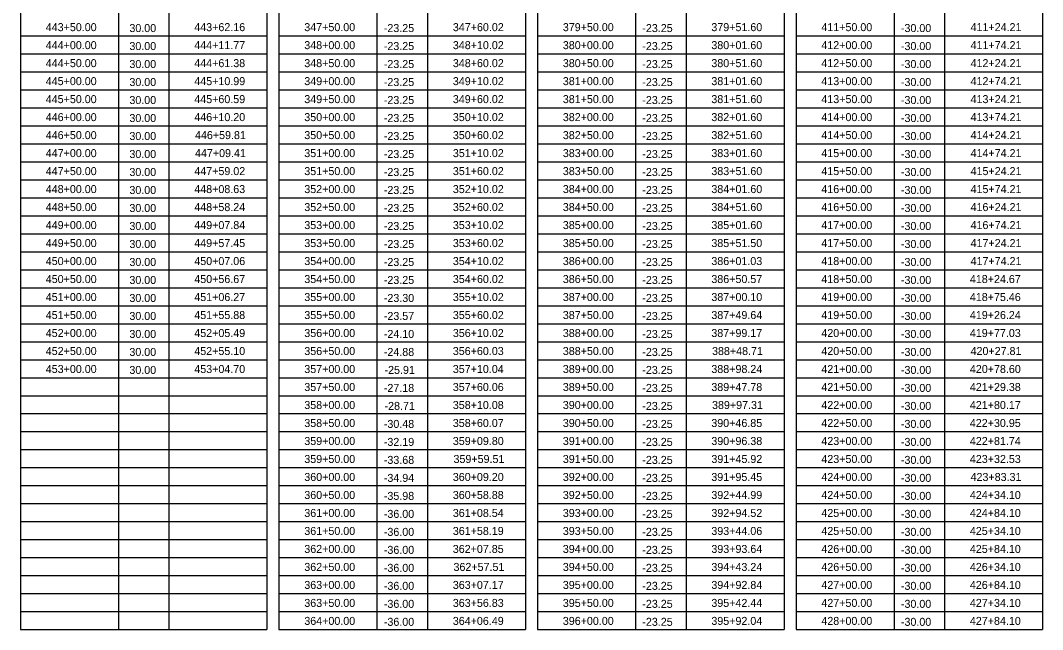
# Model space of a CAD drawing. Extents: x 1602163 to 1612907, y 1087635 to 1096265.
# Drawn here: x 1610186 to 1610952, y 1095298 to 1095755 of the extents above; entities that cross this region are included whole.
import ezdxf

# ---------------------------------------------------------------- set-up
doc = ezdxf.new("R2010")
doc.units = 0
doc.layers.add('RD_SHT_Misc1', color=7, linetype='Continuous')
doc.layers.add('RD_SHT_TX', color=7, linetype='Continuous')

msp = doc.modelspace()

# ---------------------------------------------------------------- linework, layer by layer
at = {"layer": 'RD_SHT_Misc1'}
for p, q in [((1610185.83, 1096189.84), (1610185.83, 1095297.84)), ((1610259.3, 1096189.84), (1610259.3, 1095297.84)), ((1610297.19, 1096189.84), (1610297.19, 1095297.84)), ((1610370.66, 1096189.84), (1610370.66, 1095297.84)), ((1610379.66, 1096189.84), (1610379.66, 1095297.84)), ((1610453.13, 1096189.84), (1610453.13, 1095297.84)), ((1610491.02, 1096189.84), (1610491.02, 1095297.84)), ((1610564.49, 1096189.84), (1610564.49, 1095297.84)), ((1610573.49, 1096189.84), (1610573.49, 1095297.84)), ((1610646.96, 1096189.84), (1610646.96, 1095297.84)), ((1610684.85, 1096189.84), (1610684.85, 1095297.84)), ((1610758.32, 1096189.84), (1610758.32, 1095297.84)), ((1610767.32, 1096189.84), (1610767.32, 1095297.84)), ((1610840.79, 1096189.84), (1610840.79, 1095297.84)), ((1610878.68, 1096189.84), (1610878.68, 1095297.84)), ((1610952.15, 1096189.84), (1610952.15, 1095297.84)), ((1610185.83, 1095743.34), (1610370.66, 1095743.34)), ((1610379.66, 1095743.34), (1610564.49, 1095743.34)), ((1610573.49, 1095743.34), (1610758.32, 1095743.34)), ((1610767.32, 1095743.34), (1610952.15, 1095743.34)), ((1610185.83, 1095729.84), (1610370.66, 1095729.84)), ((1610379.66, 1095729.84), (1610564.49, 1095729.84)), ((1610573.49, 1095729.84), (1610758.32, 1095729.84)), ((1610767.32, 1095729.84), (1610952.15, 1095729.84)), ((1610185.83, 1095716.34), (1610370.66, 1095716.34)), ((1610379.66, 1095716.34), (1610564.49, 1095716.34)), ((1610573.49, 1095716.34), (1610758.32, 1095716.34)), ((1610767.32, 1095716.34), (1610952.15, 1095716.34)), ((1610185.83, 1095702.84), (1610370.66, 1095702.84)), ((1610379.66, 1095702.84), (1610564.49, 1095702.84)), ((1610573.49, 1095702.84), (1610758.32, 1095702.84)), ((1610767.32, 1095702.84), (1610952.15, 1095702.84)), ((1610185.83, 1095689.34), (1610370.66, 1095689.34)), ((1610379.66, 1095689.34), (1610564.49, 1095689.34)), ((1610573.49, 1095689.34), (1610758.32, 1095689.34)), ((1610767.32, 1095689.34), (1610952.15, 1095689.34)), ((1610185.83, 1095675.84), (1610370.66, 1095675.84)), ((1610379.66, 1095675.84), (1610564.49, 1095675.84)), ((1610573.49, 1095675.84), (1610758.32, 1095675.84)), ((1610767.32, 1095675.84), (1610952.15, 1095675.84)), ((1610185.83, 1095662.34), (1610370.66, 1095662.34)), ((1610379.66, 1095662.34), (1610564.49, 1095662.34)), ((1610573.49, 1095662.34), (1610758.32, 1095662.34)), ((1610767.32, 1095662.34), (1610952.15, 1095662.34)), ((1610185.83, 1095648.84), (1610370.66, 1095648.84)), ((1610379.66, 1095648.84), (1610564.49, 1095648.84)), ((1610573.49, 1095648.84), (1610758.32, 1095648.84)), ((1610767.32, 1095648.84), (1610952.15, 1095648.84)), ((1610185.83, 1095635.34), (1610370.66, 1095635.34)), ((1610379.66, 1095635.34), (1610564.49, 1095635.34)), ((1610573.49, 1095635.34), (1610758.32, 1095635.34)), ((1610767.32, 1095635.34), (1610952.15, 1095635.34)), ((1610185.83, 1095621.84), (1610370.66, 1095621.84)), ((1610379.66, 1095621.84), (1610564.49, 1095621.84)), ((1610573.49, 1095621.84), (1610758.32, 1095621.84)), ((1610767.32, 1095621.84), (1610952.15, 1095621.84)), ((1610185.83, 1095608.34), (1610370.66, 1095608.34)), ((1610379.66, 1095608.34), (1610564.49, 1095608.34)), ((1610573.49, 1095608.34), (1610758.32, 1095608.34)), ((1610767.32, 1095608.34), (1610952.15, 1095608.34)), ((1610185.83, 1095594.84), (1610370.66, 1095594.84)), ((1610379.66, 1095594.84), (1610564.49, 1095594.84)), ((1610573.49, 1095594.84), (1610758.32, 1095594.84)), ((1610767.32, 1095594.84), (1610952.15, 1095594.84)), ((1610185.83, 1095581.34), (1610370.66, 1095581.34)), ((1610379.66, 1095581.34), (1610564.49, 1095581.34)), ((1610573.49, 1095581.34), (1610758.32, 1095581.34)), ((1610767.32, 1095581.34), (1610952.15, 1095581.34)), ((1610185.83, 1095567.84), (1610370.66, 1095567.84)), ((1610379.66, 1095567.84), (1610564.49, 1095567.84)), ((1610573.49, 1095567.84), (1610758.32, 1095567.84)), ((1610767.32, 1095567.84), (1610952.15, 1095567.84)), ((1610185.83, 1095554.34), (1610370.66, 1095554.34)), ((1610379.66, 1095554.34), (1610564.49, 1095554.34)), ((1610573.49, 1095554.34), (1610758.32, 1095554.34)), ((1610767.32, 1095554.34), (1610952.15, 1095554.34)), ((1610185.83, 1095540.84), (1610370.66, 1095540.84)), ((1610379.66, 1095540.84), (1610564.49, 1095540.84)), ((1610573.49, 1095540.84), (1610758.32, 1095540.84)), ((1610767.32, 1095540.84), (1610952.15, 1095540.84)), ((1610185.83, 1095527.34), (1610370.66, 1095527.34)), ((1610379.66, 1095527.34), (1610564.49, 1095527.34)), ((1610573.49, 1095527.34), (1610758.32, 1095527.34)), ((1610767.32, 1095527.34), (1610952.15, 1095527.34)), ((1610185.83, 1095513.84), (1610370.66, 1095513.84)), ((1610379.66, 1095513.84), (1610564.49, 1095513.84)), ((1610573.49, 1095513.84), (1610758.32, 1095513.84)), ((1610767.32, 1095513.84), (1610952.15, 1095513.84)), ((1610185.83, 1095500.34), (1610370.66, 1095500.34)), ((1610379.66, 1095500.34), (1610564.49, 1095500.34)), ((1610573.49, 1095500.34), (1610758.32, 1095500.34)), ((1610767.32, 1095500.34), (1610952.15, 1095500.34)), ((1610185.83, 1095486.84), (1610370.66, 1095486.84)), ((1610379.66, 1095486.84), (1610564.49, 1095486.84)), ((1610573.49, 1095486.84), (1610758.32, 1095486.84)), ((1610767.32, 1095486.84), (1610952.15, 1095486.84)), ((1610185.83, 1095473.34), (1610370.66, 1095473.34)), ((1610379.66, 1095473.34), (1610564.49, 1095473.34)), ((1610573.49, 1095473.34), (1610758.32, 1095473.34)), ((1610767.32, 1095473.34), (1610952.15, 1095473.34)), ((1610185.83, 1095459.84), (1610370.66, 1095459.84)), ((1610379.66, 1095459.84), (1610564.49, 1095459.84)), ((1610573.49, 1095459.84), (1610758.32, 1095459.84)), ((1610767.32, 1095459.84), (1610952.15, 1095459.84)), ((1610185.83, 1095446.34), (1610370.66, 1095446.34)), ((1610379.66, 1095446.34), (1610564.49, 1095446.34)), ((1610573.49, 1095446.34), (1610758.32, 1095446.34)), ((1610767.32, 1095446.34), (1610952.15, 1095446.34)), ((1610185.83, 1095432.84), (1610370.66, 1095432.84)), ((1610379.66, 1095432.84), (1610564.49, 1095432.84)), ((1610573.49, 1095432.84), (1610758.32, 1095432.84)), ((1610767.32, 1095432.84), (1610952.15, 1095432.84)), ((1610185.83, 1095419.34), (1610370.66, 1095419.34)), ((1610379.66, 1095419.34), (1610564.49, 1095419.34)), ((1610573.49, 1095419.34), (1610758.32, 1095419.34)), ((1610767.32, 1095419.34), (1610952.15, 1095419.34)), ((1610185.83, 1095405.84), (1610370.66, 1095405.84)), ((1610379.66, 1095405.84), (1610564.49, 1095405.84)), ((1610573.49, 1095405.84), (1610758.32, 1095405.84)), ((1610767.32, 1095405.84), (1610952.15, 1095405.84)), ((1610185.83, 1095392.34), (1610370.66, 1095392.34)), ((1610379.66, 1095392.34), (1610564.49, 1095392.34)), ((1610573.49, 1095392.34), (1610758.32, 1095392.34)), ((1610767.32, 1095392.34), (1610952.15, 1095392.34)), ((1610185.83, 1095378.84), (1610370.66, 1095378.84)), ((1610379.66, 1095378.84), (1610564.49, 1095378.84)), ((1610573.49, 1095378.84), (1610758.32, 1095378.84)), ((1610767.32, 1095378.84), (1610952.15, 1095378.84)), ((1610185.83, 1095365.34), (1610370.66, 1095365.34)), ((1610379.66, 1095365.34), (1610564.49, 1095365.34)), ((1610573.49, 1095365.34), (1610758.32, 1095365.34)), ((1610767.32, 1095365.34), (1610952.15, 1095365.34)), ((1610185.83, 1095351.84), (1610370.66, 1095351.84)), ((1610379.66, 1095351.84), (1610564.49, 1095351.84)), ((1610573.49, 1095351.84), (1610758.32, 1095351.84)), ((1610767.32, 1095351.84), (1610952.15, 1095351.84)), ((1610185.83, 1095338.34), (1610370.66, 1095338.34)), ((1610379.66, 1095338.34), (1610564.49, 1095338.34)), ((1610573.49, 1095338.34), (1610758.32, 1095338.34)), ((1610767.32, 1095338.34), (1610952.15, 1095338.34)), ((1610185.83, 1095324.84), (1610370.66, 1095324.84)), ((1610379.66, 1095324.84), (1610564.49, 1095324.84)), ((1610573.49, 1095324.84), (1610758.32, 1095324.84)), ((1610767.32, 1095324.84), (1610952.15, 1095324.84)), ((1610185.83, 1095311.34), (1610370.66, 1095311.34)), ((1610379.66, 1095311.34), (1610564.49, 1095311.34)), ((1610573.49, 1095311.34), (1610758.32, 1095311.34)), ((1610767.32, 1095311.34), (1610952.15, 1095311.34)), ((1610185.83, 1095297.84), (1610370.66, 1095297.84)), ((1610379.66, 1095297.84), (1610564.49, 1095297.84)), ((1610573.49, 1095297.84), (1610758.32, 1095297.84)), ((1610767.32, 1095297.84), (1610952.15, 1095297.84))]:
    msp.add_line(p, q, dxfattribs=at)

# ---------------------------------------------------------------- texts
at = {"layer": 'RD_SHT_TX'}
for s, p in [('443+50.00', (1610204.82, 1095746.84)), ('30.00', (1610267.52, 1095746.15)), ('443+62.16', (1610316.17, 1095746.84)), ('347+50.00', (1610398.65, 1095746.84)), ('-23.25', (1610458.26, 1095746.15)), ('347+60.02', (1610510.03, 1095746.84)), ('379+50.00', (1610592.48, 1095746.84)), ('-23.25', (1610652.09, 1095746.15)), ('379+51.60', (1610703.84, 1095746.84)), ('411+50.00', (1610786.31, 1095746.84)), ('-30.00', (1610845.95, 1095746.15)), ('411+24.21', (1610898.18, 1095746.84)), ('444+00.00', (1610204.82, 1095733.34)), ('444+11.77', (1610316.17, 1095733.34)), ('348+00.00', (1610398.65, 1095733.34)), ('348+10.02', (1610510.03, 1095733.34)), ('380+00.00', (1610592.48, 1095733.34)), ('380+01.60', (1610703.84, 1095733.34)), ('412+00.00', (1610786.31, 1095733.34)), ('411+74.21', (1610898.18, 1095733.34)), ('30.00', (1610267.52, 1095732.65)), ('-23.25', (1610458.26, 1095732.65)), ('-23.25', (1610652.09, 1095732.65)), ('-30.00', (1610845.95, 1095732.65)), ('444+50.00', (1610204.82, 1095719.84)), ('30.00', (1610267.52, 1095719.15)), ('444+61.38', (1610316.17, 1095719.84)), ('348+50.00', (1610398.65, 1095719.84)), ('-23.25', (1610458.26, 1095719.15)), ('348+60.02', (1610510.03, 1095719.84)), ('380+50.00', (1610592.48, 1095719.84)), ('-23.25', (1610652.09, 1095719.15)), ('380+51.60', (1610703.84, 1095719.84)), ('412+50.00', (1610786.31, 1095719.84)), ('-30.00', (1610845.95, 1095719.15)), ('412+24.21', (1610898.18, 1095719.84)), ('445+00.00', (1610204.82, 1095706.34)), ('30.00', (1610267.52, 1095705.65)), ('445+10.99', (1610316.17, 1095706.34)), ('349+00.00', (1610398.65, 1095706.34)), ('-23.25', (1610458.26, 1095705.65)), ('349+10.02', (1610510.03, 1095706.34)), ('381+00.00', (1610592.48, 1095706.34)), ('-23.25', (1610652.09, 1095705.65)), ('381+01.60', (1610703.84, 1095706.34)), ('413+00.00', (1610786.31, 1095706.34)), ('-30.00', (1610845.95, 1095705.65)), ('412+74.21', (1610898.18, 1095706.34)), ('445+50.00', (1610204.82, 1095692.84)), ('30.00', (1610267.52, 1095692.15)), ('445+60.59', (1610316.17, 1095692.84)), ('349+50.00', (1610398.65, 1095692.84)), ('-23.25', (1610458.26, 1095692.15)), ('349+60.02', (1610510.03, 1095692.84)), ('381+50.00', (1610592.48, 1095692.84)), ('-23.25', (1610652.09, 1095692.15)), ('381+51.60', (1610703.84, 1095692.84)), ('413+50.00', (1610786.31, 1095692.84)), ('-30.00', (1610845.95, 1095692.15)), ('413+24.21', (1610898.18, 1095692.84)), ('446+00.00', (1610204.82, 1095679.34)), ('30.00', (1610267.52, 1095678.65)), ('446+10.20', (1610316.18, 1095679.34)), ('350+00.00', (1610398.65, 1095679.34)), ('-23.25', (1610458.26, 1095678.65)), ('350+10.02', (1610510.03, 1095679.34)), ('382+00.00', (1610592.48, 1095679.34)), ('-23.25', (1610652.09, 1095678.65)), ('382+01.60', (1610703.84, 1095679.34)), ('414+00.00', (1610786.31, 1095679.34)), ('-30.00', (1610845.95, 1095678.65)), ('413+74.21', (1610898.18, 1095679.34)), ('446+50.00', (1610204.82, 1095665.84)), ('30.00', (1610267.52, 1095665.15)), ('446+59.81', (1610316.69, 1095665.84)), ('350+50.00', (1610398.65, 1095665.84)), ('-23.25', (1610458.26, 1095665.15)), ('350+60.02', (1610510.03, 1095665.84)), ('382+50.00', (1610592.48, 1095665.84)), ('-23.25', (1610652.09, 1095665.15)), ('382+51.60', (1610703.84, 1095665.84)), ('414+50.00', (1610786.31, 1095665.84)), ('-30.00', (1610845.95, 1095665.15)), ('414+24.21', (1610898.18, 1095665.84)), ('447+00.00', (1610204.82, 1095652.34)), ('30.00', (1610267.52, 1095651.65)), ('447+09.41', (1610316.69, 1095652.34)), ('351+00.00', (1610398.65, 1095652.34)), ('-23.25', (1610458.26, 1095651.65)), ('351+10.02', (1610510.03, 1095652.34)), ('383+00.00', (1610592.48, 1095652.34)), ('-23.25', (1610652.09, 1095651.65)), ('383+01.60', (1610703.84, 1095652.34)), ('415+00.00', (1610786.31, 1095652.34)), ('-30.00', (1610845.95, 1095651.65)), ('414+74.21', (1610898.18, 1095652.34)), ('447+50.00', (1610204.82, 1095638.84)), ('30.00', (1610267.52, 1095638.15)), ('447+59.02', (1610316.2, 1095638.84)), ('351+50.00', (1610398.65, 1095638.84)), ('-23.25', (1610458.26, 1095638.15)), ('351+60.02', (1610510.03, 1095638.84)), ('383+50.00', (1610592.48, 1095638.84)), ('-23.25', (1610652.09, 1095638.15)), ('383+51.60', (1610703.84, 1095638.84)), ('415+50.00', (1610786.31, 1095638.84)), ('-30.00', (1610845.95, 1095638.15)), ('415+24.21', (1610898.18, 1095638.84)), ('448+00.00', (1610204.82, 1095625.34)), ('30.00', (1610267.52, 1095624.65)), ('448+08.63', (1610316.17, 1095625.34)), ('352+00.00', (1610398.65, 1095625.34)), ('-23.25', (1610458.26, 1095624.65)), ('352+10.02', (1610510.03, 1095625.34)), ('384+00.00', (1610592.48, 1095625.34)), ('-23.25', (1610652.09, 1095624.65)), ('384+01.60', (1610703.84, 1095625.34)), ('416+00.00', (1610786.31, 1095625.34)), ('-30.00', (1610845.95, 1095624.65)), ('415+74.21', (1610898.18, 1095625.34)), ('448+50.00', (1610204.82, 1095611.84)), ('30.00', (1610267.52, 1095611.15)), ('448+58.24', (1610316.18, 1095611.84)), ('352+50.00', (1610398.65, 1095611.84)), ('-23.25', (1610458.26, 1095611.15)), ('352+60.02', (1610510.03, 1095611.84)), ('384+50.00', (1610592.48, 1095611.84)), ('-23.25', (1610652.09, 1095611.15)), ('384+51.60', (1610703.84, 1095611.84)), ('416+50.00', (1610786.31, 1095611.84)), ('-30.00', (1610845.95, 1095611.15)), ('416+24.21', (1610898.18, 1095611.84)), ('449+00.00', (1610204.82, 1095598.34)), ('30.00', (1610267.52, 1095597.65)), ('449+07.84', (1610316.18, 1095598.34)), ('353+00.00', (1610398.65, 1095598.34)), ('-23.25', (1610458.26, 1095597.65)), ('353+10.02', (1610510.03, 1095598.34)), ('385+00.00', (1610592.48, 1095598.34)), ('-23.25', (1610652.09, 1095597.65)), ('385+01.60', (1610703.84, 1095598.34)), ('417+00.00', (1610786.31, 1095598.34)), ('-30.00', (1610845.95, 1095597.65)), ('416+74.21', (1610898.18, 1095598.34)), ('449+50.00', (1610204.82, 1095584.84)), ('30.00', (1610267.52, 1095584.15)), ('449+57.45', (1610316.15, 1095584.84)), ('353+50.00', (1610398.65, 1095584.84)), ('-23.25', (1610458.26, 1095584.15)), ('353+60.02', (1610510.03, 1095584.84)), ('385+50.00', (1610592.48, 1095584.84)), ('-23.25', (1610652.09, 1095584.15)), ('385+51.50', (1610703.84, 1095584.84)), ('417+50.00', (1610786.31, 1095584.84)), ('-30.00', (1610845.95, 1095584.15)), ('417+24.21', (1610898.18, 1095584.84)), ('450+00.00', (1610204.82, 1095571.34)), ('30.00', (1610267.52, 1095570.65)), ('450+07.06', (1610316.17, 1095571.34)), ('354+00.00', (1610398.65, 1095571.34)), ('-23.25', (1610458.26, 1095570.65)), ('354+10.02', (1610510.03, 1095571.34)), ('386+00.00', (1610592.48, 1095571.34)), ('-23.25', (1610652.09, 1095570.65)), ('386+01.03', (1610703.83, 1095571.34)), ('418+00.00', (1610786.31, 1095571.34)), ('-30.00', (1610845.95, 1095570.65)), ('417+74.21', (1610898.18, 1095571.34)), ('450+50.00', (1610204.82, 1095557.84)), ('30.00', (1610267.52, 1095557.15)), ('450+56.67', (1610316.17, 1095557.84)), ('354+50.00', (1610398.65, 1095557.84)), ('-23.25', (1610458.26, 1095557.15)), ('354+60.02', (1610510.03, 1095557.84)), ('386+50.00', (1610592.48, 1095557.84)), ('-23.25', (1610652.09, 1095557.15)), ('386+50.57', (1610703.83, 1095557.84)), ('418+50.00', (1610786.31, 1095557.84)), ('-30.00', (1610845.95, 1095557.15)), ('418+24.67', (1610897.66, 1095557.84)), ('451+00.00', (1610204.82, 1095544.34)), ('30.00', (1610267.52, 1095543.65)), ('451+06.27', (1610316.17, 1095544.34)), ('355+00.00', (1610398.65, 1095544.34)), ('-23.30', (1610458.29, 1095543.65)), ('355+10.02', (1610510.03, 1095544.34)), ('387+00.00', (1610592.48, 1095544.34)), ('-23.25', (1610652.09, 1095543.65)), ('387+00.10', (1610703.84, 1095544.34)), ('419+00.00', (1610786.31, 1095544.34)), ('-30.00', (1610845.95, 1095543.65)), ('418+75.46', (1610897.66, 1095544.34)), ('451+50.00', (1610204.82, 1095530.84)), ('30.00', (1610267.52, 1095530.15)), ('451+55.88', (1610316.17, 1095530.84)), ('355+50.00', (1610398.65, 1095530.84)), ('-23.57', (1610458.28, 1095530.15)), ('355+60.02', (1610510.03, 1095530.84)), ('387+50.00', (1610592.48, 1095530.84)), ('-23.25', (1610652.09, 1095530.15)), ('387+49.64', (1610703.84, 1095530.84)), ('419+50.00', (1610786.31, 1095530.84)), ('-30.00', (1610845.95, 1095530.15)), ('419+26.24', (1610897.67, 1095530.84)), ('452+00.00', (1610204.82, 1095517.34)), ('30.00', (1610267.52, 1095516.65)), ('452+05.49', (1610316.17, 1095517.34)), ('356+00.00', (1610398.65, 1095517.34)), ('-24.10', (1610458.29, 1095516.65)), ('356+10.02', (1610510.03, 1095517.34)), ('388+00.00', (1610592.48, 1095517.34)), ('-23.25', (1610652.09, 1095516.65)), ('387+99.17', (1610703.83, 1095517.34)), ('420+00.00', (1610786.31, 1095517.34)), ('-30.00', (1610845.95, 1095516.65)), ('419+77.03', (1610897.66, 1095517.34)), ('452+50.00', (1610204.82, 1095503.84)), ('452+55.10', (1610316.18, 1095503.84)), ('356+50.00', (1610398.65, 1095503.84)), ('356+60.03', (1610510, 1095503.84)), ('388+50.00', (1610592.48, 1095503.84)), ('388+48.71', (1610704.35, 1095503.84)), ('420+50.00', (1610786.31, 1095503.84)), ('420+27.81', (1610898.18, 1095503.84)), ('30.00', (1610267.52, 1095503.15)), ('-24.88', (1610458.28, 1095503.15)), ('-23.25', (1610652.09, 1095503.15)), ('-30.00', (1610845.95, 1095503.15)), ('453+00.00', (1610204.82, 1095490.34)), ('30.00', (1610267.52, 1095489.65)), ('453+04.70', (1610316.18, 1095490.34)), ('357+00.00', (1610398.65, 1095490.34)), ('-25.91', (1610458.8, 1095489.65)), ('357+10.04', (1610510.01, 1095490.34)), ('389+00.00', (1610592.48, 1095490.34)), ('-23.25', (1610652.09, 1095489.65)), ('388+98.24', (1610703.84, 1095490.34)), ('421+00.00', (1610786.31, 1095490.34)), ('-30.00', (1610845.95, 1095489.65)), ('420+78.60', (1610897.67, 1095490.34)), ('357+50.00', (1610398.65, 1095476.84)), ('-27.18', (1610458.28, 1095476.15)), ('357+60.06', (1610510, 1095476.84)), ('389+50.00', (1610592.48, 1095476.84)), ('-23.25', (1610652.09, 1095476.15)), ('389+47.78', (1610703.83, 1095476.84)), ('421+50.00', (1610786.31, 1095476.84)), ('-30.00', (1610845.95, 1095476.15)), ('421+29.38', (1610897.66, 1095476.84)), ('358+00.00', (1610398.65, 1095463.34)), ('-28.71', (1610458.8, 1095462.65)), ('358+10.08', (1610510, 1095463.34)), ('390+00.00', (1610592.48, 1095463.34)), ('-23.25', (1610652.09, 1095462.65)), ('389+97.31', (1610704.35, 1095463.34)), ('422+00.00', (1610786.31, 1095463.34)), ('-30.00', (1610845.95, 1095462.65)), ('421+80.17', (1610897.66, 1095463.34)), ('358+50.00', (1610398.65, 1095449.84)), ('358+60.07', (1610510, 1095449.84)), ('390+50.00', (1610592.48, 1095449.84)), ('390+46.85', (1610703.81, 1095449.84)), ('422+50.00', (1610786.31, 1095449.84)), ('422+30.95', (1610897.64, 1095449.84)), ('-30.48', (1610458.28, 1095449.15)), ('-23.25', (1610652.09, 1095449.15)), ('-30.00', (1610845.95, 1095449.15)), ('359+00.00', (1610398.65, 1095436.34)), ('-32.19', (1610458.28, 1095435.65)), ('359+09.80', (1610510.01, 1095436.34)), ('391+00.00', (1610592.48, 1095436.34)), ('-23.25', (1610652.09, 1095435.65)), ('390+96.38', (1610703.83, 1095436.34)), ('423+00.00', (1610786.31, 1095436.34)), ('-30.00', (1610845.95, 1095435.65)), ('422+81.74', (1610897.67, 1095436.34)), ('359+50.00', (1610398.65, 1095422.84)), ('-33.68', (1610458.28, 1095422.15)), ('359+59.51', (1610510.52, 1095422.84)), ('391+50.00', (1610592.48, 1095422.84)), ('-23.25', (1610652.09, 1095422.15)), ('391+45.92', (1610703.86, 1095422.84)), ('423+50.00', (1610786.31, 1095422.84)), ('-30.00', (1610845.95, 1095422.15)), ('423+32.53', (1610897.66, 1095422.84)), ('360+00.00', (1610398.65, 1095409.34)), ('-34.94', (1610458.29, 1095408.65)), ('360+09.20', (1610510.01, 1095409.34)), ('392+00.00', (1610592.48, 1095409.34)), ('-23.25', (1610652.09, 1095408.65)), ('391+95.45', (1610703.81, 1095409.34)), ('424+00.00', (1610786.31, 1095409.34)), ('-30.00', (1610845.95, 1095408.65)), ('423+83.31', (1610898.18, 1095409.34)), ('360+50.00', (1610398.65, 1095395.84)), ('-35.98', (1610458.28, 1095395.15)), ('360+58.88', (1610510, 1095395.84)), ('392+50.00', (1610592.48, 1095395.84)), ('-23.25', (1610652.09, 1095395.15)), ('392+44.99', (1610703.83, 1095395.84)), ('424+50.00', (1610786.31, 1095395.84)), ('-30.00', (1610845.95, 1095395.15)), ('424+34.10', (1610897.67, 1095395.84)), ('361+00.00', (1610398.65, 1095382.34)), ('-36.00', (1610458.29, 1095381.65)), ('361+08.54', (1610510.01, 1095382.34)), ('393+00.00', (1610592.48, 1095382.34)), ('-23.25', (1610652.09, 1095381.65)), ('392+94.52', (1610703.86, 1095382.34)), ('425+00.00', (1610786.31, 1095382.34)), ('-30.00', (1610845.95, 1095381.65)), ('424+84.10', (1610897.67, 1095382.34)), ('361+50.00', (1610398.65, 1095368.84)), ('-36.00', (1610458.29, 1095368.15)), ('361+58.19', (1610510, 1095368.84)), ('393+50.00', (1610592.48, 1095368.84)), ('-23.25', (1610652.09, 1095368.15)), ('393+44.06', (1610703.83, 1095368.84)), ('425+50.00', (1610786.31, 1095368.84)), ('-30.00', (1610845.95, 1095368.15)), ('425+34.10', (1610897.67, 1095368.84)), ('362+00.00', (1610398.65, 1095355.34)), ('-36.00', (1610458.29, 1095354.65)), ('362+07.85', (1610509.98, 1095355.34)), ('394+00.00', (1610592.48, 1095355.34)), ('-23.25', (1610652.09, 1095354.65)), ('393+93.64', (1610703.84, 1095355.34)), ('426+00.00', (1610786.31, 1095355.34)), ('-30.00', (1610845.95, 1095354.65)), ('425+84.10', (1610897.67, 1095355.34)), ('362+50.00', (1610398.65, 1095341.84)), ('-36.00', (1610458.29, 1095341.15)), ('362+57.51', (1610510.52, 1095341.84)), ('394+50.00', (1610592.48, 1095341.84)), ('-23.25', (1610652.09, 1095341.15)), ('394+43.24', (1610703.84, 1095341.84)), ('426+50.00', (1610786.31, 1095341.84)), ('-30.00', (1610845.95, 1095341.15)), ('426+34.10', (1610897.67, 1095341.84)), ('363+00.00', (1610398.65, 1095328.34)), ('-36.00', (1610458.29, 1095327.65)), ('363+07.17', (1610510, 1095328.34)), ('395+00.00', (1610592.48, 1095328.34)), ('-23.25', (1610652.09, 1095327.65)), ('394+92.84', (1610703.84, 1095328.34)), ('427+00.00', (1610786.31, 1095328.34)), ('-30.00', (1610845.95, 1095327.65)), ('426+84.10', (1610897.67, 1095328.34)), ('363+50.00', (1610398.65, 1095314.84)), ('-36.00', (1610458.29, 1095314.15)), ('363+56.83', (1610510, 1095314.84)), ('395+50.00', (1610592.48, 1095314.84)), ('-23.25', (1610652.09, 1095314.15)), ('395+42.44', (1610703.84, 1095314.84)), ('427+50.00', (1610786.31, 1095314.84)), ('-30.00', (1610845.95, 1095314.15)), ('427+34.10', (1610897.67, 1095314.84)), ('364+00.00', (1610398.65, 1095301.34)), ('-36.00', (1610458.29, 1095300.65)), ('364+06.49', (1610510, 1095301.34)), ('396+00.00', (1610592.48, 1095301.34)), ('-23.25', (1610652.09, 1095300.65)), ('395+92.04', (1610703.84, 1095301.34)), ('428+00.00', (1610786.31, 1095301.34)), ('-30.00', (1610845.95, 1095300.65)), ('427+84.10', (1610897.67, 1095301.34))]:
    msp.add_text(s, height=6, dxfattribs=at).set_placement(p)

doc.saveas('drawing.dxf')
